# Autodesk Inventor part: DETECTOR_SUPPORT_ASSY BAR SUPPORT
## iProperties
Shininess: 64.0
Length Units: 11272
Angle Units: 11279
Time Units: 11290
Mass Units: 11286
Length Display Precision: 3
Angle Display Precision: 2
Compacted: True
Part Number: DETECTOR_SUPPORT_ASSY BAR SUPPORT
Document SubType Name: Modeling
Created: 2004-08
Designer: John Blackburn
Material: ALUMINUM
Manufacturer: Standard
Standards Organization: Custom
Density: 0.0
Volumn: 0.0
Area: 0.0
PropertySet Name: Model Information
Control State: 0
Master: False
Checked Out: False
Author: John Blackburn
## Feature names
1. ExtrusionBlind1
2. ExtrusionThru1
3. ExtrusionThru2
4. Chamfer1
